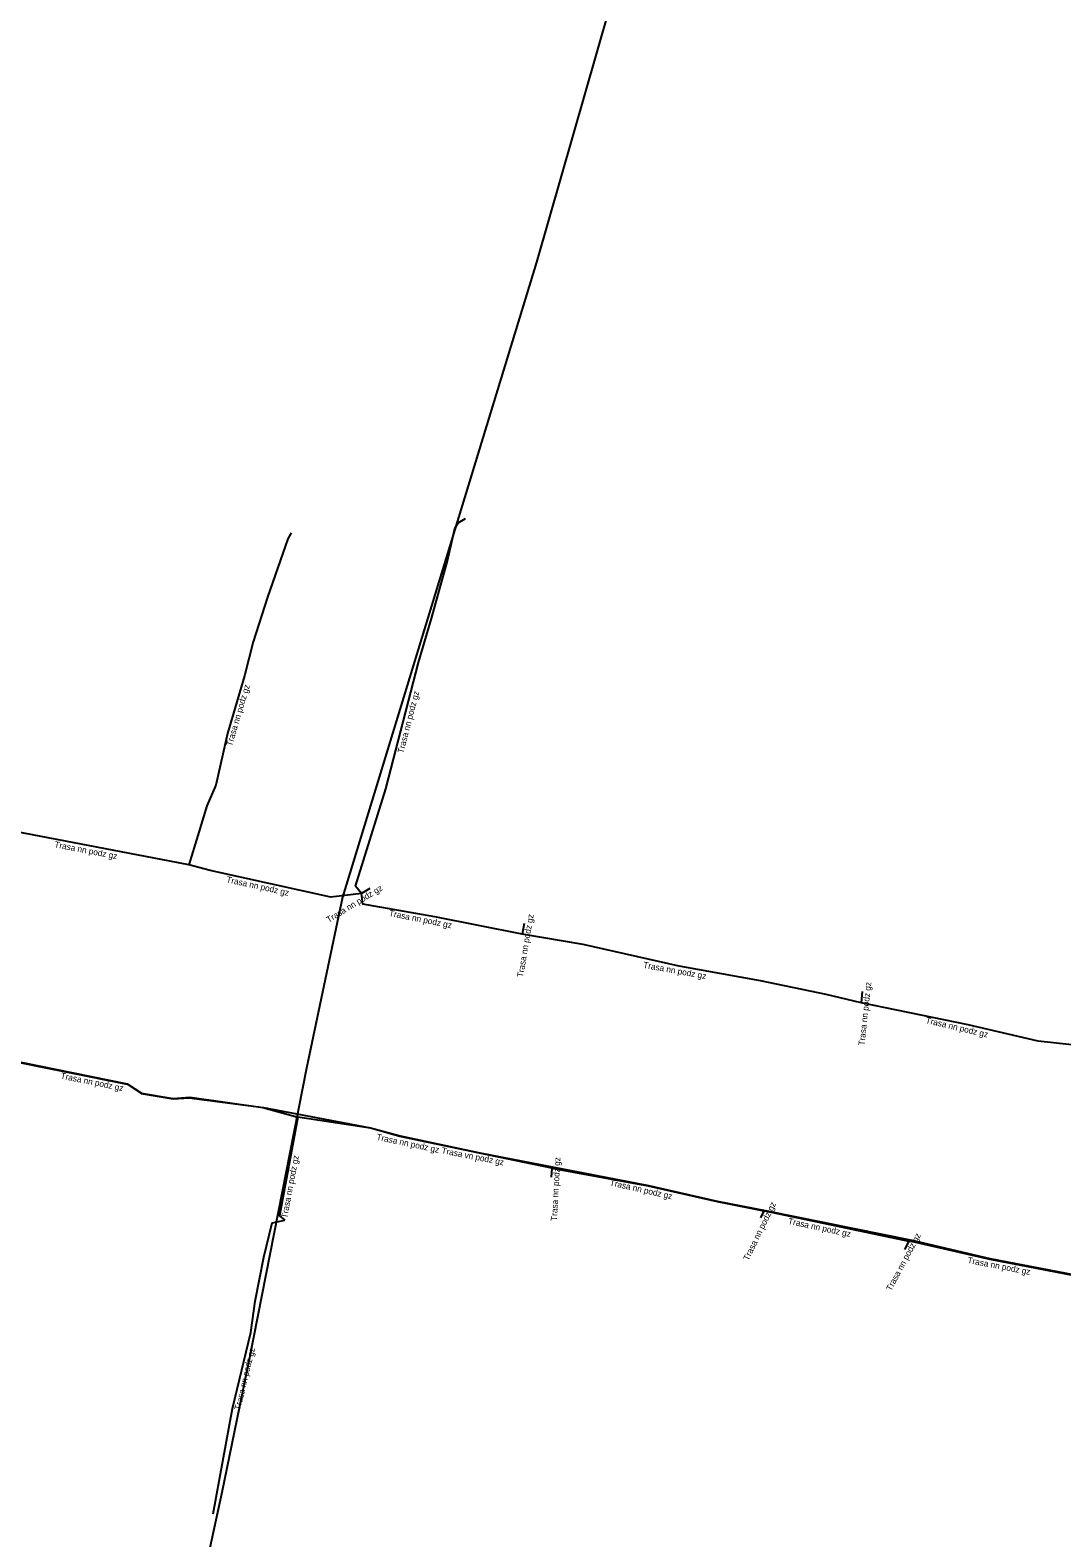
# Model space of a CAD drawing. Extents: x -687924 to -686708, y -1056742 to -1056249.
# Drawn here: x -687116.2 to -687032.8, y -1056536.2 to -1056414.3 of the extents above; entities that cross this region are included whole.
import ezdxf

# ---------------------------------------------------------------- set-up
doc = ezdxf.new("R2010")
doc.units = 0
for name, color, linetype in [('Popiskový text - Ostatní atributy Trasy', 7, 'Continuous'), ('Spojnice NN', 7, 'Continuous'), ('Spojnice VN', 7, 'Continuous')]:
    doc.layers.add(name, color=color, linetype=linetype)

msp = doc.modelspace()

# ---------------------------------------------------------------- linework, layer by layer
at = {"layer": 'Spojnice NN'}
for points in [[(-687089.43, -1056484.11), (-687089.92, -1056483.52), (-687087.45, -1056475.65), (-687084.82, -1056465.43), (-687083.78, -1056461.87), (-687082.48, -1056457.18), (-687081.88, -1056454.59), (-687081.61, -1056454.11), (-687081.01, -1056453.76)], [(-687095.12, -1056454.93), (-687095.38, -1056455.42), (-687097.02, -1056460.13), (-687098.19, -1056463.74), (-687098.89, -1056466.5), (-687100.27, -1056471.16), (-687101.21, -1056475.35), (-687101.94, -1056477.01), (-687102.67, -1056479.42), (-687103.4, -1056481.79)], [(-687103.4, -1056481.79), (-687104.94, -1056481.5), (-687117.29, -1056479.12)], [(-687089.43, -1056484.11), (-687091.91, -1056484.39), (-687101.66, -1056482.25), (-687103.4, -1056481.79)], [(-687088.76, -1056483.7), (-687089.43, -1056484.11)], [(-687076.43, -1056487.4), (-687083.5, -1056486), (-687089.32, -1056484.97), (-687089.43, -1056484.11)], [(-687076.28, -1056486.52), (-687076.43, -1056487.4)], [(-687049.04, -1056492.94), (-687051.87, -1056492.27), (-687057.17, -1056491.18), (-687063.75, -1056489.98), (-687071.5, -1056488.24), (-687076.43, -1056487.4)], [(-687048.94, -1056492.02), (-687049.04, -1056492.94)], [(-687030.75, -1056496.49), (-687034.72, -1056496.05), (-687040.39, -1056494.72), (-687049.04, -1056492.94)], [(-687125.27, -1056496.02), (-687118.44, -1056497.46), (-687108.38, -1056499.51), (-687107.23, -1056500.26), (-687104.67, -1056500.69), (-687103.31, -1056500.58), (-687097.4, -1056501.42), (-687094.57, -1056502.21)], [(-687094.57, -1056502.21), (-687096.06, -1056510.18), (-687095.64, -1056510.52)], [(-687074.05, -1056506.31), (-687079.9, -1056505.12), (-687086.33, -1056503.76), (-687088.71, -1056503.1), (-687094.57, -1056502.21)], [(-687074.05, -1056506.31), (-687074.09, -1056507.04)], [(-687074.05, -1056506.31), (-687066.24, -1056507.75), (-687060.66, -1056509.02), (-687056.89, -1056509.77)], [(-687056.89, -1056509.77), (-687057.17, -1056510.35)], [(-687056.89, -1056509.77), (-687056.67, -1056509.8), (-687045.17, -1056512.23)], [(-687101.41, -1056534.28), (-687099.87, -1056525.77), (-687098.38, -1056519.61), (-687098.02, -1056517.08), (-687097.33, -1056513.52), (-687096.66, -1056510.74), (-687095.64, -1056510.52)], [(-687045.17, -1056512.23), (-687045.52, -1056512.89)], [(-687045.17, -1056512.23), (-687044.89, -1056512.25), (-687038.63, -1056513.68), (-687031.77, -1056515), (-687029.65, -1056515.49), (-687027.82, -1056515.81)]]:
    msp.add_lwpolyline(points, dxfattribs=at)
at = {"layer": 'Spojnice VN'}
for points in [[(-687063.58, -1056392.2), (-687075.27, -1056433.04), (-687090.96, -1056484.41), (-687093.89, -1056498.24), (-687098.49, -1056521.67), (-687100.73, -1056532.56), (-687105.71, -1056555.55), (-687109.47, -1056581.05), (-687116.2, -1056610.91)], [(-687166.79, -1056487.57), (-687160.61, -1056488.8), (-687153.93, -1056490.24), (-687148.09, -1056491.4), (-687139.64, -1056493.12), (-687131.37, -1056494.68), (-687125.6, -1056495.92), (-687118.44, -1056497.5), (-687108.39, -1056499.54), (-687107.25, -1056500.28), (-687104.67, -1056500.71), (-687103.36, -1056500.62), (-687097.35, -1056501.42), (-687088.7, -1056503.06), (-687086.31, -1056503.72), (-687079.86, -1056505.07), (-687074.02, -1056506.21), (-687066.23, -1056507.72), (-687060.66, -1056508.98), (-687056.66, -1056509.77), (-687044.93, -1056512.15), (-687038.62, -1056513.64), (-687031.75, -1056514.95)]]:
    msp.add_lwpolyline(points, dxfattribs=at)

# ---------------------------------------------------------------- texts
at = {"layer": 'Popiskový text - Ostatní atributy Trasy'}
for s, rotation, p in [('Trasa nn podz gz', 73.504, (-687099.91, -1056472.23)), ('Trasa nn podz gz', 75.5687, (-687086.04, -1056472.8)), ('Trasa nn podz gz', 349.0921, (-687114.29, -1056480.36)), ('Trasa nn podz gz', 347.6206, (-687100.39, -1056483.19)), ('Trasa nn podz gz', 31.4641, (-687092.08, -1056486.49)), ('Trasa nn podz gz', 348.7992, (-687087.24, -1056485.92)), ('Trasa nn podz gz', 80.3266, (-687076.37, -1056490.91)), ('Trasa nn podz gz', 349.6645, (-687066.68, -1056490.11)), ('Trasa nn podz gz', 83.7966, (-687048.76, -1056496.42)), ('Trasa nn podz gz', 346.7989, (-687043.85, -1056494.58)), ('Trasa nn podz gz', 348.4848, (-687113.79, -1056499.07)), ('Trasa nn podz gz', 348.0138, (-687088.25, -1056504.02)), ('Trasa vn podz gz', 348.9544, (-687082.99, -1056505.12)), ('Trasa nn podz gz', 79.4107, (-687095.44, -1056510.41)), ('Trasa nn podz gz', 86.8636, (-687073.63, -1056510.6)), ('Trasa nn podz gz', 347.2381, (-687069.39, -1056507.71)), ('Trasa nn podz gz', 64.2106, (-687058.14, -1056513.85)), ('Trasa nn podz gz', 348.0886, (-687054.97, -1056510.83)), ('Trasa nn podz gz', 62.0629, (-687046.6, -1056516.3)), ('Trasa nn podz gz', 349.1437, (-687040.46, -1056513.99)), ('Trasa nn podz gz', 76.4023, (-687099.24, -1056525.93))]:
    msp.add_text(s, height=0.5, rotation=rotation, dxfattribs=at).set_placement(p)

doc.saveas('drawing.dxf')
